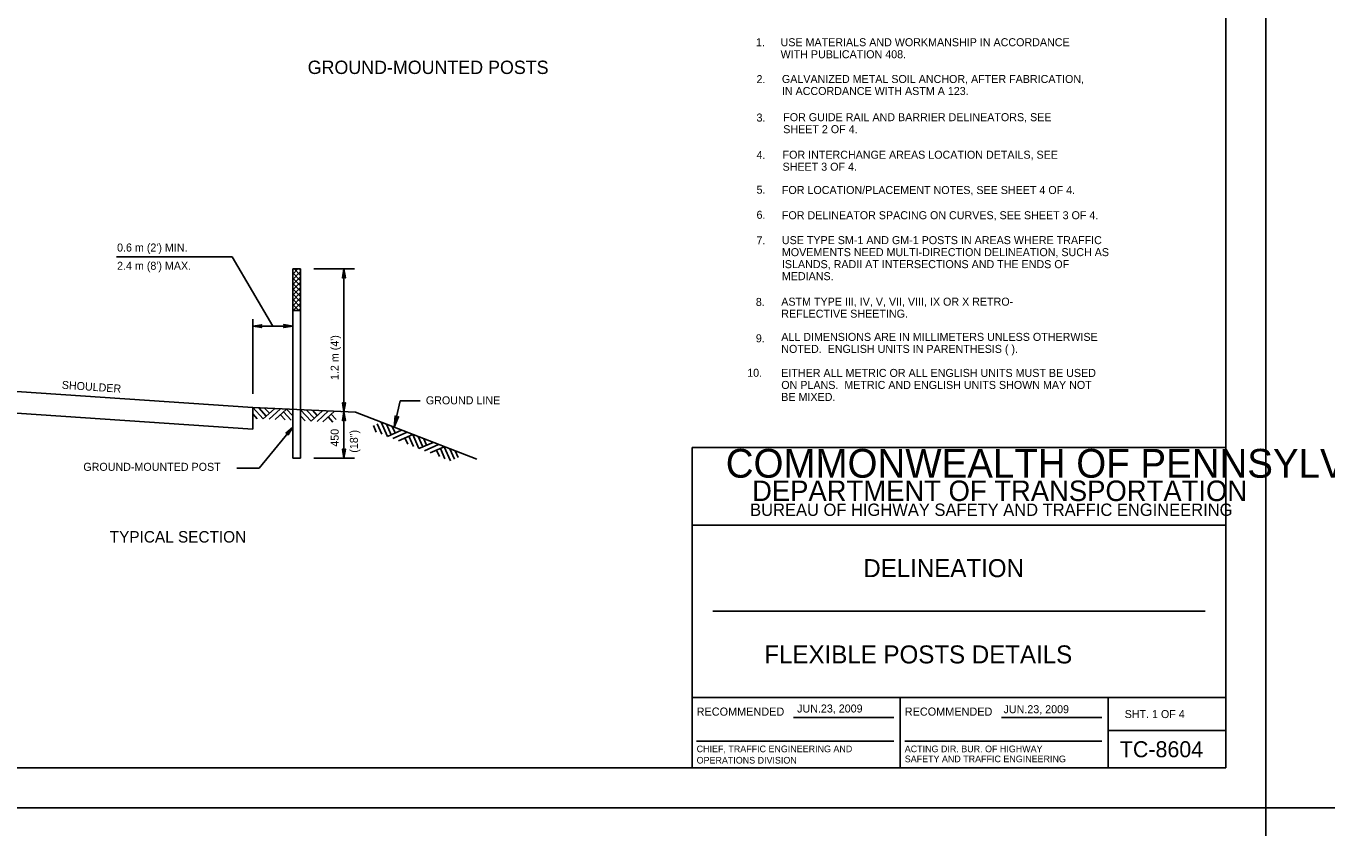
# Model space of a CAD drawing. Extents: x 640253 to 641999, y 298458 to 299646.
# Drawn here: x 640629.6 to 641116.9, y 299044.1 to 299344.6 of the extents above; entities that cross this region are included whole.
import ezdxf

# ---------------------------------------------------------------- set-up
doc = ezdxf.new("R2010")
doc.units = 0
for name, color, linetype in [('1', 7, 'Continuous'), ('2', 7, 'Continuous'), ('PLT-BNDY', 7, 'Continuous')]:
    doc.layers.add(name, color=color, linetype=linetype)

msp = doc.modelspace()

# ---------------------------------------------------------------- linework, layer by layer
at = {"layer": '1'}
for p, q in [((641079.31, 299066.63), (641079.31, 299630.63)), ((640879.31, 299066.63), (640879.31, 299186.63)), ((640879.31, 299186.63), (641079.31, 299186.63)), ((641079.31, 299157.63), (640879.31, 299157.63)), ((640887.06, 299125.31), (641071.56, 299125.31)), ((640879.31, 299093), (641079.31, 299093)), ((640957.31, 299093), (640957.31, 299066.63)), ((641035.19, 299066.63), (641035.19, 299093)), ((640917.24, 299085.57), (640954.87, 299085.57)), ((640995.24, 299085.57), (641032.87, 299085.57)), ((641035.19, 299080.63), (641079.31, 299080.63)), ((640880.99, 299076.68), (640954.87, 299076.68)), ((640958.99, 299076.68), (641032.87, 299076.68)), ((641079.31, 299066.63), (640293.31, 299066.63)), ((640293.31, 299066.63), (640879.31, 299066.63))]:
    msp.add_line(p, q, dxfattribs=at)
at = {"layer": '2'}
for p, q in [((640663.62, 299258.11), (640706.89, 299258.11)), ((640722.13, 299232.16), (640706.89, 299258.11)), ((640729.61, 299253.58), (640732.55, 299253.58)), ((640729.61, 299237.99), (640729.61, 299253.58)), ((640729.61, 299251.64), (640731.55, 299253.58)), ((640729.61, 299249.66), (640732.55, 299252.6)), ((640732.55, 299251.14), (640730.12, 299253.58)), ((640732.55, 299253.12), (640732.1, 299253.58)), ((640732.55, 299237.99), (640732.55, 299253.58)), ((640737.54, 299253.58), (640752.77, 299253.58)), ((640748.8, 299253.58), (640748.8, 299200.09)), ((640732.55, 299249.16), (640729.61, 299252.1)), ((640729.61, 299247.68), (640732.55, 299250.62)), ((640732.55, 299247.18), (640729.61, 299250.12)), ((640729.61, 299245.7), (640732.55, 299248.64)), ((640732.55, 299245.2), (640729.61, 299248.14)), ((640729.61, 299243.72), (640732.55, 299246.66)), ((640732.55, 299243.22), (640729.61, 299246.16)), ((640729.61, 299241.74), (640732.55, 299244.68)), ((640732.55, 299241.24), (640729.61, 299244.18)), ((640729.61, 299239.76), (640732.55, 299242.7)), ((640732.55, 299239.26), (640729.61, 299242.2)), ((640731.85, 299237.99), (640729.61, 299240.22)), ((640729.86, 299237.99), (640729.61, 299238.25)), ((640729.61, 299237.99), (640732.55, 299237.99)), ((640729.61, 299182.73), (640729.61, 299237.99)), ((640729.83, 299237.99), (640732.55, 299240.72)), ((640731.81, 299237.99), (640732.55, 299238.74)), ((640732.55, 299182.73), (640732.55, 299237.99)), ((640714.64, 299234.74), (640714.64, 299206.78)), ((640714.64, 299232.16), (640729.61, 299232.16)), ((640605.44, 299208.99), (640714.64, 299201.64)), ((640767.69, 299194.24), (640769.87, 299204.1)), ((640769.87, 299204.1), (640777.37, 299204.1)), ((640605.44, 299200.94), (640714.64, 299193.59)), ((640714.64, 299193.59), (640714.64, 299201.64)), ((640714.64, 299201.64), (640753.14, 299199.89)), ((640714.64, 299201.64), (640718.57, 299197.35)), ((640714.64, 299199.31), (640716.34, 299197.45)), ((640716.86, 299201.54), (640719.72, 299198.41)), ((640722.8, 299201.21), (640718.56, 299197.35)), ((640719.08, 299201.44), (640720.88, 299199.48)), ((640725.09, 299201.16), (640720.79, 299197.25)), ((640727.32, 299201.06), (640723.02, 299197.15)), ((640724.99, 299198.93), (640726.78, 299196.98)), ((640726.15, 299200), (640729.01, 299196.88)), ((640727.32, 299201.06), (640729.61, 299198.55)), ((640732.55, 299200.83), (640736.48, 299196.54)), ((640734.78, 299200.72), (640737.64, 299197.6)), ((640740.71, 299200.4), (640736.47, 299196.54)), ((640737, 299200.63), (640738.8, 299198.66)), ((640743, 299200.35), (640738.71, 299196.43)), ((640745.23, 299200.25), (640740.93, 299196.33)), ((640744.07, 299199.18), (640745.88, 299197.2)), ((640748.8, 299182.73), (640748.8, 299200.09)), ((640753.14, 299199.89), (640798.56, 299182.25)), ((640717.02, 299178.97), (640729.61, 299194.34)), ((640732.55, 299198.49), (640734.25, 299196.63)), ((640742.91, 299198.12), (640744.7, 299196.16)), ((640759.85, 299194.88), (640760.93, 299192.46)), ((640761.3, 299195.52), (640763.01, 299191.65)), ((640762.74, 299196.16), (640765.09, 299190.85)), ((640764.81, 299195.36), (640766.52, 299191.48)), ((640766.88, 299194.56), (640767.96, 299192.12)), ((640770.33, 299193.15), (640765.08, 299190.85)), ((640772.48, 299192.38), (640767.16, 299190.04)), ((640774.57, 299191.57), (640769.25, 299189.23)), ((640771.68, 299190.29), (640772.75, 299187.87)), ((640773.12, 299190.93), (640774.83, 299187.06)), ((640774.57, 299191.57), (640776.91, 299186.25)), ((640776.64, 299190.76), (640778.35, 299186.89)), ((640778.71, 299189.96), (640779.79, 299187.53)), ((640782.23, 299188.59), (640776.91, 299186.26)), ((640784.23, 299187.75), (640778.99, 299185.44)), ((640786.39, 299186.98), (640781.07, 299184.64)), ((640783.51, 299185.7), (640784.57, 299183.28)), ((640784.95, 299186.34), (640786.66, 299182.47)), ((640786.39, 299186.98), (640788.74, 299181.66)), ((640788.46, 299186.17), (640790.18, 299182.3)), ((640790.54, 299185.37), (640791.61, 299182.93)), ((640729.61, 299182.73), (640732.55, 299182.73)), ((640737.54, 299182.73), (640752.77, 299182.73)), ((640708.68, 299178.97), (640717.02, 299178.97))]:
    msp.add_line(p, q, dxfattribs=at)
for points in [[(640748.4, 299250.38), (640748.63, 299250.5), (640748.8, 299253.58), (640748.4, 299250.38), (640748.26, 299250.22), (640748.8, 299253.58), (640748.95, 299250.5), (640749.18, 299250.39), (640748.8, 299253.58), (640749.34, 299250.22), (640749.18, 299250.39)], [(640717.83, 299231.76), (640717.72, 299231.99), (640714.64, 299232.16), (640717.83, 299231.76), (640718, 299231.62), (640714.64, 299232.16), (640717.71, 299232.31), (640717.83, 299232.54), (640714.64, 299232.16), (640718, 299232.69), (640717.83, 299232.54)], [(640726.42, 299232.56), (640726.53, 299232.33), (640729.61, 299232.16), (640726.42, 299232.56), (640726.25, 299232.7), (640729.61, 299232.16), (640726.54, 299232.01), (640726.43, 299231.78), (640729.61, 299232.16), (640726.25, 299231.62), (640726.43, 299231.78)], [(640748.4, 299196.89), (640748.63, 299197.01), (640748.8, 299200.09), (640748.4, 299196.89), (640748.26, 299196.73), (640748.8, 299200.09), (640748.95, 299197.01), (640749.18, 299196.9), (640748.8, 299200.09), (640749.34, 299196.73), (640749.18, 299196.9)], [(640749.2, 299203.28), (640748.97, 299203.17), (640748.8, 299200.09), (640749.2, 299203.28), (640749.34, 299203.45), (640748.8, 299200.09), (640748.65, 299203.16), (640748.42, 299203.28), (640748.8, 299200.09), (640748.27, 299203.45), (640748.42, 299203.28)], [(640727.28, 299192.12), (640727.53, 299192.06), (640729.61, 299194.34), (640727.28, 299192.12), (640727.07, 299192.08), (640729.61, 299194.34), (640727.78, 299191.86), (640727.89, 299191.63), (640729.61, 299194.34), (640727.9, 299191.4), (640727.89, 299191.63)], [(640769.04, 299198.03), (640768.73, 299197.95), (640767.69, 299194.24), (640769.04, 299198.03), (640769.26, 299198.2), (640767.69, 299194.24), (640768.33, 299198.03), (640768.08, 299198.23), (640767.69, 299194.24), (640767.95, 299198.48), (640768.08, 299198.23)], [(640749.2, 299185.93), (640748.97, 299185.81), (640748.8, 299182.73), (640749.2, 299185.93), (640749.34, 299186.1), (640748.8, 299182.73), (640748.65, 299185.81), (640748.42, 299185.92), (640748.8, 299182.73), (640748.27, 299186.1), (640748.42, 299185.92)]]:
    msp.add_lwpolyline(points, dxfattribs=at)
at = {"layer": 'PLT-BNDY'}
for points in [[(640253.31, 299645.63), (641094.31, 299645.63), (641094.31, 299051.63), (640253.31, 299051.63)], [(641094.31, 299645.63), (641935.31, 299645.63), (641935.31, 299051.63), (641094.31, 299051.63)], [(640253.31, 299051.63), (641094.31, 299051.63), (641094.31, 298457.63), (640253.31, 298457.63)], [(641094.31, 299051.63), (641935.31, 299051.63), (641935.31, 298457.63), (641094.31, 298457.63)]]:
    msp.add_lwpolyline(points, close=True, dxfattribs=at)

# ---------------------------------------------------------------- texts
at = {"layer": '1'}
for s, height, p in [('COMMONWEALTH OF PENNSYLVANIA', 10.7828, (640891.9, 299175.36)), ('DEPARTMENT OF TRANSPORTATION', 7.6837, (640901.76, 299166.61)), ('BUREAU OF HIGHWAY SAFETY AND TRAFFIC ENGINEERING', 4.6253, (640901.04, 299161.04)), ('DELINEATION', 6.75, (640943.46, 299138.1)), ('FLEXIBLE POSTS DETAILS', 6.75, (640906.36, 299105.78)), ('RECOMMENDED', 3.048, (640880.99, 299086.2)), ('JUN.23, 2009', 3, (640918.65, 299087.39)), ('RECOMMENDED', 3.048, (640958.99, 299086.2)), ('JUN.23, 2009', 3, (640996.01, 299087.13)), ('SHT. 1 OF 4', 3, (641041.4, 299085.31)), ('CHIEF, TRAFFIC ENGINEERING AND', 2.5, (640880.99, 299072.51)), ('ACTING DIR. BUR. OF HIGHWAY', 2.5, (640958.99, 299072.51)), ('TC-8604', 6, (641039.6, 299070.63)), ('OPERATIONS DIVISION', 2.5, (640880.99, 299068.26)), ('SAFETY AND TRAFFIC ENGINEERING', 2.5, (640958.99, 299068.76))]:
    msp.add_text(s, height=height, dxfattribs=at).set_placement(p)
at = {"layer": '2'}
for s, height, p in [('USE MATERIALS AND WORKMANSHIP IN ACCORDANCE', 3, (640912.45, 299337)), ('1.', 3, (640903.23, 299337)), ('WITH PUBLICATION 408.', 3, (640912.45, 299332.5)), ('GROUND-MOUNTED POSTS', 5, (640735.22, 299326.6)), ('2.', 3, (640903.43, 299323.18)), ('GALVANIZED METAL SOIL ANCHOR, AFTER FABRICATION,', 3, (640912.94, 299323.23)), ('IN ACCORDANCE WITH ASTM A 123.', 3, (640912.94, 299318.73)), ('3.', 3, (640903.43, 299308.78)), ('FOR GUIDE RAIL AND BARRIER DELINEATORS, SEE', 3, (640913.44, 299308.92)), ('SHEET 2 OF 4.', 3, (640913.44, 299304.42)), ('4.', 3, (640903.43, 299294.77)), ('FOR INTERCHANGE AREAS LOCATION DETAILS, SEE', 3, (640913.19, 299294.86)), ('SHEET 3 OF 4.', 3, (640913.19, 299290.36)), ('5.', 3, (640903.43, 299281.75)), ('FOR LOCATION/PLACEMENT NOTES, SEE SHEET 4 OF 4.', 3, (640912.94, 299281.64)), ('6.', 3, (640903.43, 299272.36)), ('FOR DELINEATOR SPACING ON CURVES, SEE SHEET 3 OF 4.', 3, (640912.94, 299272.19)), ("0.6 m (2') MIN.", 3, (640663.78, 299260.09)), ('7.', 3, (640903.43, 299262.79)), ('USE TYPE SM-1 AND GM-1 POSTS IN AREAS WHERE TRAFFIC', 3, (640912.94, 299262.86)), ('MOVEMENTS NEED MULTI-DIRECTION DELINEATION, SUCH AS', 3, (640912.94, 299258.36)), ("2.4 m (8') MAX.", 3, (640663.78, 299253.25)), ('MEDIANS.', 3, (640912.94, 299249.36)), ('ISLANDS, RADII AT INTERSECTIONS AND THE ENDS OF', 3, (640912.94, 299253.86)), ('8.', 3, (640903.18, 299239.71)), ('ASTM TYPE III, IV, V, VII, VIII, IX OR X RETRO-', 3, (640912.7, 299239.81)), ('REFLECTIVE SHEETING.', 3, (640912.7, 299235.31)), ('9.', 3, (640903.18, 299226.08)), ('ALL DIMENSIONS ARE IN MILLIMETERS UNLESS OTHERWISE', 3, (640912.71, 299226.61)), ('NOTED.  ENGLISH UNITS IN PARENTHESIS ( ).', 3, (640912.71, 299222.11)), ('10.', 3, (640899.94, 299213.16)), ('EITHER ALL METRIC OR ALL ENGLISH UNITS MUST BE USED', 3, (640912.71, 299213.11)), ('ON PLANS.  METRIC AND ENGLISH UNITS SHOWN MAY NOT ', 3, (640912.71, 299208.61)), ('GROUND LINE', 3, (640779.51, 299202.84)), ('BE MIXED.', 3, (640912.71, 299204.11)), ('GROUND-MOUNTED POST', 3, (640651.13, 299177.93)), ('TYPICAL SECTION', 4.3, (640661.04, 299151.06))]:
    msp.add_text(s, height=height, dxfattribs=at).set_placement(p)
for s, rotation, p in [("1.2 m (4')", 90, (640746.83, 299211.95)), ('SHOULDER', 356.1494, (640642.99, 299208.68)), ('450', 90, (640746.83, 299186.97)), ('(18")', 90, (640754.03, 299184.71))]:
    msp.add_text(s, height=3, rotation=rotation, dxfattribs=at).set_placement(p)

doc.saveas('drawing.dxf')
